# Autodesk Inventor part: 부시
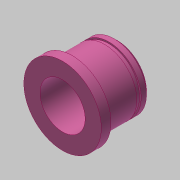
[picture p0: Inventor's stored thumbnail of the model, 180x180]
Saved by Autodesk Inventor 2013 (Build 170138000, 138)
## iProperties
Created: 2019-01
Part Number: 부시
Material: 강철, 연강
Document SubType Name: Modeling
Designer: mduedu
Density: 7.86 g/cm^3
Mass: 23.9234 g
Surface Area: 24.4489 cm^2
Volume: 3.04369 cm^3
Author: mduedu
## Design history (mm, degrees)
sketch "스케치1"
  geometry: L1 (0, 0)-(3, 0); L2 (3, 0)-(3, 12); L3 (3, 12)-(0, 12); L4 (0, 12)-(0, 0); L5 (3, 0)-(17, 0); L6 (17, 0)-(17, 10); L7 (17, 10)-(3, 10); L8 (3, 10)-(3, 0)
  constraints: 16 end point, 4 parallel, 2 horizontal, 2 perpendicular
  dimensions: "d0" = 17 distance between parallel lines of L6 L4; "d2" = 3 distance of L2.end L3.end; "d3" = 24 diameter of L3 L1; "d4" = 20 diameter of L7 L5
revolve "회전1" sketch "스케치1" stored, may be unused: angle "d5" = 90 deg
sketch "스케치2"
  geometry: C1 r 7 at (0, 0); 1 further point
  constraints: 1 centre point, 1 coincident
  dimensions: "d6" = 14 diameter of C1
extrude "돌출1" cut sketch "스케치2" stored distance "d7" = 10; taper "d8" = 0 deg
chamfer "모따기1" distance "d9" = 1; stored, may be unused: second distance "d10" = 2, angle "d11" = 45 deg
node "작업 평면1"
sketch "스케치3"
  geometry: C1 r 9.5 at (0, 0); C2 r 10 at (0, 0) reference; 1 further point
  constraints: 1 centre point, 1 coincident
  dimensions: "d13" = 19 diameter of C1
extrude "돌출2" cut sketch "스케치3" distance "d14" = 1.35; taper "d15" = 0 deg
node "솔리드1"
